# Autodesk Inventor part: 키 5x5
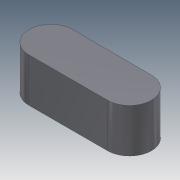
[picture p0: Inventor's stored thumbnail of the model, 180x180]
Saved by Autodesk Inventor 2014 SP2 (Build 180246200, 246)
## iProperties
Company: 한국ATC센터
Created: 2014-10
Part Number: 키 5x5
Document SubType Name: Modeling
Designer: KYOUNG IL JANG
Density: 1 g/cm^3
Mass: 0.323175 g
Surface Area: 2.9781 cm^2
Volume: 0.323175 cm^3
Material: 일반
Appearance: 강철 - 광택
Author: KYOUNG IL JANG
Revision Number: 1
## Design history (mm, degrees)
sketch "스케치1"
  geometry: L1 (-4.5, -2.5)-(4.5, -2.5); L2 (4.5, 2.5)-(-4.5, 2.5); A1 r 2.5 centre (4.5, 0) between (4.5, -2.5) and (4.5, 2.5); A2 r 2.5 centre (-4.5, 0) between (-4.5, 2.5) and (-4.5, -2.5); 2 further points
  constraints: 4 end point, 4 point on circle, 4 tangent, 2 centre point, 1 horizontal, 1 horizontal alignment, 1 midpoint, 1 parallel, 1 vertical alignment
  dimensions: "d0" = 5 distance between parallel lines of L1 L2; "d1" = 14 dimension on A1 A2
extrude "돌출1" new body sketch "스케치1" stored distance "d2" = 5; taper "d3" = 0 deg
node "솔리드1"
